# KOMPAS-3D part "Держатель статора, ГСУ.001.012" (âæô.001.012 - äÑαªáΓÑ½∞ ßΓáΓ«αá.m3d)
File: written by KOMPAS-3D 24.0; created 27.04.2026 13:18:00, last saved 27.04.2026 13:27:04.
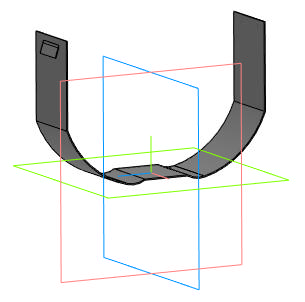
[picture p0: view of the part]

Document properties: Автор: User7; Полное имя файла: C:\Users\User7\Desktop\олимп\ГСУ.001.012 - Держатель статора.m3d

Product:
- Part/product: Держатель статора  | designation ГСУ.001.012
    Масса: 0.004314

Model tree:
1. Эскиз:1
2. Элемент выдавливания:1
     Толщина стенки 1 = 0.3; Расстояние 1 = 16
3. Эскиз:2  (with: Вершина.Элемент выдавливания:1, Ребро.Элемент выдавливания:1)
4. Элемент выдавливания:2
     Толщина стенки 2 = 0.2; Расстояние 1 = 8
5. Зеркальный массив:1
6. Экземпляр ( 1 )
7. Экземпляр ( 2 )  (with: Элемент выдавливания:2, Элемент выдавливания:1)

Expressions: 11.8/2; 55/2
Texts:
  ГСУ.001.012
